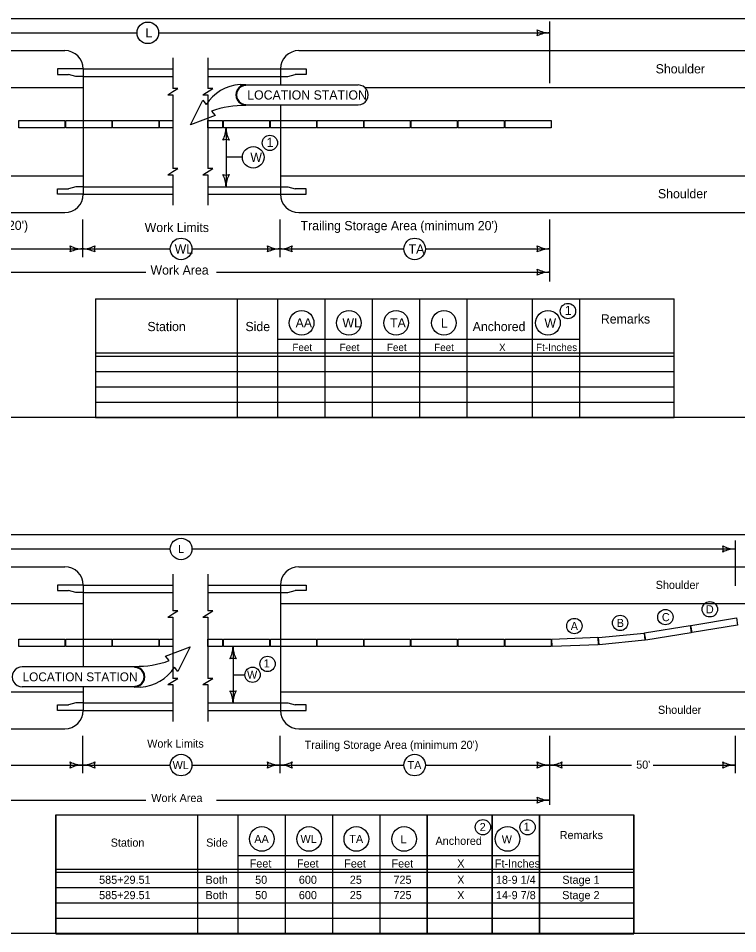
# Model space of a CAD drawing. Extents: x 8045 to 81668, y 6217 to 16762.
# Drawn here: x 14916 to 16087, y 6217 to 7708 of the extents above; entities that cross this region are included whole.
import ezdxf

# ---------------------------------------------------------------- set-up
doc = ezdxf.new("R2010")
doc.units = 0
for name, color, linetype in [('dsnNonPlotable', 7, 'Continuous'), ('dsnStdBlockModified', 7, 'Continuous'), ('dsnStdBlockNotModified', 7, 'Continuous'), ('dsnStdBorder', 7, 'Continuous'), ('dsnStdLineWork', 7, 'Continuous'), ('Level 2', 7, 'Continuous'), ('Level 5', 7, 'Continuous')]:
    doc.layers.add(name, color=color, linetype=linetype)

msp = doc.modelspace()

# ---------------------------------------------------------------- linework, layer by layer
at = {"layer": 'dsnNonPlotable'}
for p, q in [((15781, 7703.1), (15781, 7602.2)), ((14230.5, 7684.4), (15109, 7684.4)), ((15144.3, 7684.4), (15781, 7684.4)), ((13862.8, 7655.5), (14991.3, 7655.5)), ((15372.7, 7655.5), (16721.1, 7655.5)), ((15167.3, 7643.5), (15167.3, 7593.6)), ((15224.4, 7643.5), (15224.4, 7593.6)), ((15021.3, 7625.5), (14979.3, 7625.5)), ((14979.3, 7625.5), (14979.3, 7616.5)), ((15021.3, 7625.5), (15021.3, 7421.5)), ((15021.3, 7625.5), (15167.3, 7625.5)), ((15224.4, 7625.5), (15342.7, 7625.5)), ((15342.7, 7625.5), (15384.7, 7625.5)), ((15342.7, 7625.5), (15342.7, 7599.5)), ((15384.7, 7625.5), (15384.7, 7616.5)), ((14979.3, 7616.5), (14997.3, 7616.5)), ((15009.3, 7613.5), (14997.3, 7616.5)), ((15021.3, 7613.5), (15009.3, 7613.5)), ((15021.3, 7613.5), (15167.3, 7613.5)), ((15224.4, 7613.5), (15342.7, 7613.5)), ((15342.7, 7613.5), (15354.7, 7613.5)), ((15354.7, 7613.5), (15366.7, 7616.5)), ((15384.7, 7616.5), (15366.7, 7616.5)), ((13779.2, 7595.5), (15021.3, 7595.5)), ((15167.3, 7588.6), (15175.3, 7593.6)), ((15175.3, 7593.6), (15167.3, 7593.6)), ((15216.4, 7583.5), (15232.4, 7593.6)), ((15232.4, 7593.6), (15224.4, 7593.6)), ((15276.8, 7600), (15286.3, 7600.4)), ((15286.3, 7600.4), (15286.3, 7598.6)), ((15286.3, 7599.5), (15469.4, 7599.5)), ((15480.2, 7595.5), (16811.5, 7595.5)), ((15159.3, 7583.5), (15167.3, 7588.6)), ((15159.3, 7583.5), (15167.3, 7583.5)), ((15167.3, 7583.5), (15167.3, 7523.5)), ((15195.9, 7534.5), (15216, 7574.5)), ((15216, 7574.5), (15221.6, 7567.5)), ((15216.4, 7583.5), (15224.4, 7583.5)), ((15224.4, 7583.5), (15224.4, 7523.5)), ((15286.3, 7567.9), (15286.3, 7566.1)), ((15286.3, 7567), (15469.4, 7567)), ((15342.7, 7567), (15342.7, 7421.5)), ((15236.1, 7549.5), (15195.9, 7534.5)), ((15230.2, 7556.8), (15236.1, 7549.5)), ((15254, 7529.8), (15254, 7433.5)), ((15167.3, 7523.5), (15167.3, 7463.4)), ((15224.4, 7523.5), (15224.4, 7463.4)), ((15280.6, 7481.6), (15254, 7481.6)), ((15159.3, 7453.3), (15167.3, 7458.4)), ((15167.3, 7458.4), (15175.3, 7463.4)), ((15175.3, 7463.4), (15167.3, 7463.4)), ((15216.4, 7453.3), (15232.4, 7463.4)), ((15232.4, 7463.4), (15224.4, 7463.4)), ((13779.2, 7451.5), (15021.3, 7451.5)), ((15159.3, 7453.3), (15167.3, 7453.3)), ((15167.3, 7453.3), (15167.3, 7403.5)), ((15216.4, 7453.3), (15224.4, 7453.3)), ((15224.4, 7453.3), (15224.4, 7403.5)), ((15342.7, 7451.5), (16811.5, 7451.5)), ((14979.3, 7430.5), (14997.3, 7430.5)), ((14979.3, 7421.5), (14979.3, 7430.5)), ((15009.3, 7433.5), (14997.3, 7430.5)), ((15021.3, 7433.5), (15009.3, 7433.5)), ((15021.3, 7433.5), (15167.3, 7433.5)), ((15224.4, 7433.5), (15342.7, 7433.5)), ((15342.7, 7433.5), (15354.7, 7433.5)), ((15354.7, 7433.5), (15366.7, 7430.5)), ((15384.7, 7430.5), (15366.7, 7430.5)), ((15384.7, 7421.5), (15384.7, 7430.5)), ((15021.3, 7421.5), (14979.3, 7421.5)), ((15021.3, 7421.5), (15167.3, 7421.5)), ((15224.4, 7421.5), (15342.7, 7421.5)), ((15342.7, 7421.5), (15384.7, 7421.5)), ((13862.8, 7391.5), (14991.3, 7391.5)), ((15372.7, 7391.5), (16721.1, 7391.5)), ((15020.1, 7380.2), (15020.1, 7319)), ((15341.5, 7380.2), (15341.5, 7319)), ((15781, 7380.2), (15781, 7279.4)), ((14794, 7332.4), (15020.1, 7332.4)), ((15020.1, 7332.4), (15163.3, 7332.4)), ((15198.3, 7332.4), (15341.5, 7332.4)), ((15211, 7332.4), (15341.5, 7332.4)), ((15341.5, 7332.4), (15543.6, 7332.4)), ((15578.9, 7332.4), (15781, 7332.4)), ((14532.6, 7294.5), (15123.4, 7294.5)), ((15238.7, 7294.5), (15781, 7294.5)), ((15240.1, 7294.5), (15341.5, 7294.5)), ((15272.6, 7058), (15272.6, 7251)), ((15338.6, 7058), (15338.6, 7251)), ((15415.6, 7058), (15415.6, 7251)), ((15492.6, 7058), (15492.6, 7251)), ((15569.6, 7058), (15569.6, 7251)), ((15338.6, 7185.2), (15830.1, 7185.2)), ((15041.6, 7163), (15984.1, 7163)), ((15041.6, 7158), (15984.1, 7158))]:
    msp.add_line(p, q, dxfattribs=at)
for points in [[(14916.3, 7541.8), (14991.3, 7541.8), (14991.3, 7529.8), (14916.3, 7529.8)], [(14992.8, 7541.8), (15067.8, 7541.8), (15067.8, 7529.8), (14992.8, 7529.8)], [(15069.3, 7541.8), (15144.3, 7541.8), (15144.3, 7529.8), (15069.3, 7529.8)], [(15249.7, 7541.8), (15324.7, 7541.8), (15324.7, 7529.8), (15249.7, 7529.8)], [(15326.2, 7541.8), (15401.2, 7541.8), (15401.2, 7529.8), (15326.2, 7529.8)], [(15402.7, 7541.8), (15477.7, 7541.8), (15477.7, 7529.8), (15402.7, 7529.8)], [(15479.2, 7541.8), (15554.2, 7541.8), (15554.2, 7529.8), (15479.2, 7529.8)], [(15555.7, 7541.8), (15630.7, 7541.8), (15630.7, 7529.8), (15555.7, 7529.8)], [(15632.2, 7541.8), (15707.2, 7541.8), (15707.2, 7529.8), (15632.2, 7529.8)], [(15708.7, 7541.8), (15783.7, 7541.8), (15783.7, 7529.8), (15708.7, 7529.8)]]:
    msp.add_lwpolyline(points, close=True, dxfattribs=at)
for points in [[(15167.3, 7529.8), (15145.8, 7529.8), (15145.8, 7541.8), (15167.3, 7541.8)], [(15167.3, 7541.8), (15167.3, 7529.8)], [(15224.4, 7529.8), (15224.4, 7541.8)], [(15224.4, 7541.8), (15248.2, 7541.8), (15248.2, 7529.8), (15224.4, 7529.8)]]:
    msp.add_lwpolyline(points, dxfattribs=at)
for centre, radius in [((15126.6, 7684.4), 17.6), ((15325.4, 7505.1), 12.5), ((15298.3, 7481.6), 17.6), ((15180.8, 7332.4), 17.6), ((15561.3, 7332.4), 17.6), ((15377.1, 7212), 20.1), ((15454.1, 7212), 20.1), ((15531.1, 7212), 20.1), ((15608.9, 7212), 20.1), ((15778.4, 7212), 20.1), ((15811, 7231.2), 12.5)]:
    msp.add_circle(centre, radius, dxfattribs=at)
for centre, radius, start, end in [((15745.4, 7684.4), 16.4, 342.2666, 17.7333), ((15781, 7726.9), 42.5, 241.9275, 270), ((15781, 7641.9), 42.5, 90, 118.0725), ((14991.3, 7625.5), 30, 0, 90), ((15372.7, 7625.5), 30, 90, 180), ((15211.5, 7529.8), 42.5, 331.9275, 0), ((15296.5, 7529.8), 42.5, 180, 208.0725), ((15254, 7494.1), 16.4, 72.2666, 107.7334), ((15254, 7469.1), 16.4, 252.2666, 287.7334), ((15211.5, 7433.5), 42.5, 0, 28.0725), ((15296.5, 7433.5), 42.5, 151.9275, 180), ((14991.3, 7421.5), 30, 270, 360), ((15372.7, 7421.5), 30, 180, 270), ((14984.5, 7332.4), 16.4, 342.2666, 17.7333), ((15020.1, 7374.9), 42.5, 241.9275, 270), ((15020.1, 7374.9), 42.5, 270, 298.0725), ((15055.8, 7332.4), 16.4, 162.2666, 197.7334), ((15305.9, 7332.4), 16.4, 342.2666, 17.7333), ((15341.5, 7374.9), 42.5, 241.9275, 270), ((15341.5, 7374.9), 42.5, 270, 298.0725), ((15377.1, 7332.4), 16.4, 162.2666, 197.7334), ((15745.4, 7332.4), 16.4, 342.2666, 17.7333), ((15781, 7374.9), 42.5, 241.9275, 270), ((15020.1, 7289.9), 42.5, 90, 118.0725), ((15020.1, 7289.9), 42.5, 61.9275, 90), ((15341.5, 7289.9), 42.5, 90, 118.0725), ((15341.5, 7289.9), 42.5, 61.9275, 90), ((15781, 7289.9), 42.5, 90, 118.0725), ((15745.4, 7294.5), 16.4, 342.2666, 17.7333), ((15781, 7337), 42.5, 241.9275, 270), ((15781, 7252), 42.5, 90, 118.0725)]:
    msp.add_arc(centre, radius, start, end, dxfattribs=at)
for centre, major_axis, start_param, end_param in [((15281.3, 7529.7), (-70.8, 0), 4.776871, 5.71778), ((15286.3, 7583.2), (-16.3, 0), 4.712389, 7.853982), ((15286.3, 7583.2), (15.4, 0), 1.570796, 4.712389), ((15469.4, 7583.2), (16.3, 0), 4.712389, 7.853982), ((15283.5, 7410), (-156.9, 0), 4.694293, 5.059134)]:
    msp.add_ellipse(centre, major_axis=major_axis, ratio=0.995025, start_param=start_param, end_param=end_param, dxfattribs=at)
at = {"layer": 'dsnStdBlockModified'}
msp.add_line((13747.5, 7708), (16852.5, 7708), dxfattribs=at)
at = {"layer": 'dsnStdBlockNotModified'}
for p, q in [((15041.6, 7133), (15984.1, 7133)), ((15041.6, 7108), (15984.1, 7108)), ((15041.6, 7083), (15984.1, 7083)), ((15041.6, 7058), (15984.1, 7058))]:
    msp.add_line(p, q, dxfattribs=at)
at = {"layer": 'dsnStdBorder'}
msp.add_line((16852.5, 7058), (13747.5, 7058), dxfattribs=at)
at = {"layer": 'dsnStdLineWork'}
for p, q in [((13747.5, 6867.4), (16852.5, 6867.4)), ((14230.5, 6843.7), (15163.3, 6843.7)), ((15198.3, 6843.7), (16083.2, 6843.7)), ((15211, 6843.7), (15341.5, 6843.7)), ((16083.2, 6857.6), (16083.2, 6783.9)), ((13862.8, 6814.8), (14991.3, 6814.8)), ((15372.7, 6814.8), (16721.1, 6814.8)), ((15167.3, 6802.8), (15167.3, 6742.8)), ((15224.4, 6802.8), (15224.4, 6742.8)), ((15021.3, 6784.8), (14979.3, 6784.8)), ((14979.3, 6784.8), (14979.3, 6775.8)), ((15021.3, 6784.8), (15167.3, 6784.8)), ((15021.3, 6784.8), (15021.3, 6651.7)), ((15224.4, 6784.8), (15342.7, 6784.8)), ((15342.7, 6784.8), (15384.7, 6784.8)), ((15342.7, 6784.8), (15342.7, 6580.8)), ((15384.7, 6784.8), (15384.7, 6775.8)), ((14979.3, 6775.8), (14997.3, 6775.8)), ((15009.3, 6772.8), (14997.3, 6775.8)), ((15021.3, 6772.8), (15009.3, 6772.8)), ((15021.3, 6772.8), (15167.3, 6772.8)), ((15224.4, 6772.8), (15342.7, 6772.8)), ((15342.7, 6772.8), (15354.7, 6772.8)), ((15354.7, 6772.8), (15366.7, 6775.8)), ((15384.7, 6775.8), (15366.7, 6775.8)), ((13779.2, 6754.8), (15021.3, 6754.8)), ((15342.7, 6754.8), (16811.5, 6754.8)), ((15167.3, 6737.8), (15175.3, 6742.8)), ((15175.3, 6742.8), (15167.3, 6742.8)), ((15216.4, 6732.7), (15232.4, 6742.8)), ((15232.4, 6742.8), (15224.4, 6742.8)), ((15159.3, 6732.7), (15167.3, 6737.8)), ((15159.3, 6732.7), (15167.3, 6732.7)), ((15167.3, 6732.7), (15167.3, 6682.8)), ((15216.4, 6732.7), (15224.4, 6732.7)), ((15224.4, 6732.7), (15224.4, 6682.8)), ((15155.5, 6669.2), (15195.7, 6684.2)), ((15167.3, 6682.8), (15167.3, 6632.8)), ((15195.7, 6684.2), (15175.6, 6644.2)), ((15224.4, 6682.8), (15224.4, 6632.8)), ((15265.4, 6684.8), (15265.4, 6592.8)), ((15161.4, 6661.8), (15155.5, 6669.2)), ((15105.2, 6651.7), (14922.1, 6651.7)), ((15105.2, 6650.8), (15105.2, 6652.6)), ((15175.6, 6644.2), (15169.9, 6651.2)), ((15265.4, 6638.8), (15284.7, 6638.8)), ((15159.3, 6622.7), (15167.3, 6627.8)), ((15159.3, 6622.7), (15167.3, 6622.7)), ((15167.3, 6627.8), (15175.3, 6632.8)), ((15175.3, 6632.8), (15167.3, 6632.8)), ((15167.3, 6622.7), (15167.3, 6562.8)), ((15216.4, 6622.7), (15232.4, 6632.8)), ((15216.4, 6622.7), (15224.4, 6622.7)), ((15232.4, 6632.8), (15224.4, 6632.8)), ((15224.4, 6622.7), (15224.4, 6562.8)), ((13779.2, 6610.8), (15021.3, 6610.8)), ((15105.2, 6619.2), (14922.1, 6619.2)), ((15021.3, 6619.2), (15021.3, 6580.8)), ((15105.2, 6618.3), (15105.2, 6620.1)), ((15114.7, 6618.6), (15105.2, 6618.3)), ((15342.7, 6610.8), (16811.5, 6610.8)), ((15009.3, 6592.8), (14997.3, 6589.8)), ((15021.3, 6592.8), (15009.3, 6592.8)), ((15021.3, 6592.8), (15167.3, 6592.8)), ((15224.4, 6592.8), (15342.7, 6592.8)), ((15342.7, 6592.8), (15354.7, 6592.8)), ((15354.7, 6592.8), (15366.7, 6589.8)), ((14979.3, 6589.8), (14997.3, 6589.8)), ((14979.3, 6580.8), (14979.3, 6589.8)), ((15021.3, 6580.8), (14979.3, 6580.8)), ((15021.3, 6580.8), (15167.3, 6580.8)), ((15224.4, 6580.8), (15342.7, 6580.8)), ((15342.7, 6580.8), (15384.7, 6580.8)), ((15384.7, 6589.8), (15366.7, 6589.8)), ((15384.7, 6580.8), (15384.7, 6589.8)), ((13862.8, 6550.8), (14991.3, 6550.8)), ((15372.7, 6550.8), (16721.1, 6550.8)), ((15020.1, 6539.5), (15020.1, 6478.3)), ((15341.5, 6539.5), (15341.5, 6478.3)), ((15781, 6539.5), (15781, 6427.1)), ((16083.2, 6539.5), (16083.2, 6478.3)), ((14794, 6491.7), (15020.1, 6491.7)), ((15020.1, 6491.7), (15163.3, 6491.7)), ((15198.3, 6491.7), (15341.5, 6491.7)), ((15211, 6491.7), (15341.5, 6491.7)), ((15341.5, 6491.7), (15543.6, 6491.7)), ((15578.9, 6491.7), (15781, 6491.7)), ((15781, 6491.7), (15914.4, 6491.7)), ((15949.7, 6491.7), (16083.2, 6491.7)), ((14532.6, 6434.6), (15123.4, 6434.6)), ((15238.7, 6434.6), (15781, 6434.6)), ((15240.1, 6434.6), (15341.5, 6434.6)), ((14976.8, 6410.4), (14976.8, 6217.4)), ((14976.8, 6410.4), (15918.4, 6410.4)), ((14976.8, 6217.4), (14976.8, 6410.4)), ((14976.8, 6410.4), (15918.4, 6410.4)), ((15207.8, 6217.4), (15207.8, 6410.4)), ((15273.8, 6217.4), (15273.8, 6410.4)), ((15350.8, 6217.4), (15350.8, 6410.4)), ((15427.8, 6217.4), (15427.8, 6410.4)), ((15504.8, 6217.4), (15504.8, 6410.4)), ((15581.8, 6217.4), (15581.8, 6410.4)), ((15581.8, 6410.4), (15581.8, 6217.4)), ((15687.4, 6217.4), (15687.4, 6410.4)), ((15687.4, 6410.4), (15687.4, 6217.4)), ((15764.4, 6217.4), (15764.4, 6410.4)), ((15764.4, 6410.4), (15764.4, 6217.4)), ((15918.4, 6217.4), (15918.4, 6410.4)), ((15918.4, 6410.4), (15918.4, 6217.4)), ((15273.8, 6344.6), (15764.4, 6344.6)), ((14976.8, 6322.4), (15918.4, 6322.4)), ((14976.8, 6317.4), (15918.4, 6317.4)), ((14976.8, 6292.4), (15918.4, 6292.4)), ((14976.8, 6267.4), (15918.4, 6267.4)), ((14976.8, 6242.4), (15918.4, 6242.4)), ((16852.5, 6217.4), (13747.5, 6217.4)), ((14976.8, 6217), (15918.4, 6217))]:
    msp.add_line(p, q, dxfattribs=at)
for points in [[(16011.4, 6719.3), (16085.4, 6731.4), (16087.4, 6719.6), (16013.4, 6707.5)], [(15935.9, 6706.9), (16009.9, 6719.1), (16011.9, 6707.2), (15937.9, 6695.1)], [(14916.3, 6696.8), (14991.3, 6696.8), (14991.3, 6684.8), (14916.3, 6684.8)], [(14992.8, 6696.8), (15067.8, 6696.8), (15067.8, 6684.8), (14992.8, 6684.8)], [(15069.3, 6696.8), (15144.3, 6696.8), (15144.3, 6684.8), (15069.3, 6684.8)], [(15249.7, 6696.8), (15324.7, 6696.8), (15324.7, 6684.8), (15249.7, 6684.8)], [(15326.2, 6696.8), (15401.2, 6696.8), (15401.2, 6684.8), (15326.2, 6684.8)], [(15402.7, 6696.8), (15477.7, 6696.8), (15477.7, 6684.8), (15402.7, 6684.8)], [(15479.2, 6696.8), (15554.2, 6696.8), (15554.2, 6684.8), (15479.2, 6684.8)], [(15555.7, 6696.8), (15630.7, 6696.8), (15630.7, 6684.8), (15555.7, 6684.8)], [(15632.2, 6696.8), (15707.2, 6696.8), (15707.2, 6684.8), (15632.2, 6684.8)], [(15708.7, 6696.8), (15783.7, 6696.8), (15783.7, 6684.8), (15708.7, 6684.8)], [(15784.7, 6696.8), (15859.7, 6699.8), (15860.2, 6687.8), (15785.2, 6684.8)], [(15860.5, 6699.7), (15935.2, 6706.8), (15936.3, 6694.9), (15861.7, 6687.8)]]:
    msp.add_lwpolyline(points, close=True, dxfattribs=at)
for points in [[(15167.3, 6684.8), (15145.8, 6684.8), (15145.8, 6696.8), (15167.3, 6696.8)], [(15167.3, 6696.8), (15167.3, 6684.8)], [(15224.4, 6684.8), (15224.4, 6696.8)], [(15224.4, 6696.8), (15248.2, 6696.8), (15248.2, 6684.8), (15224.4, 6684.8)]]:
    msp.add_lwpolyline(points, dxfattribs=at)
for centre, radius in [((15180.8, 6843.7), 17.6), ((16042.1, 6745.4), 12.5), ((15969.7, 6732.7), 12.5), ((15821.4, 6718.2), 12.5), ((15896, 6723.2), 12.5), ((15321.6, 6656.4), 12.5), ((15297.2, 6638.8), 12.5), ((15180.8, 6491.7), 17.6), ((15561.3, 6491.7), 17.6), ((15672.4, 6390.5), 12.5), ((15745.2, 6390.5), 12.5), ((15312.3, 6371.4), 20.1), ((15389.3, 6371.4), 20.1), ((15466.3, 6371.4), 20.1), ((15544.1, 6371.4), 20.1), ((15712.6, 6371.4), 20.1)]:
    msp.add_circle(centre, radius, dxfattribs=at)
for centre, radius, start, end in [((16047.5, 6843.7), 16.4, 342.2666, 17.7333), ((16083.2, 6886.2), 42.5, 241.9275, 270), ((16083.2, 6801.2), 42.5, 90, 118.0725), ((14991.3, 6784.8), 30, 0, 90), ((15372.7, 6784.8), 30, 90, 180), ((15222.9, 6684.8), 42.5, 331.9275, 360), ((15307.9, 6684.8), 42.5, 180, 208.0725), ((15265.4, 6649.1), 16.4, 72.2666, 107.7334), ((15265.4, 6628.4), 16.4, 252.2666, 287.7333), ((15222.9, 6592.8), 42.5, 360, 28.0725), ((15307.9, 6592.8), 42.5, 151.9275, 180), ((14991.3, 6580.8), 30, 270, 360), ((15372.7, 6580.8), 30, 180, 270), ((14984.5, 6491.7), 16.4, 342.2666, 17.7333), ((15020.1, 6534.2), 42.5, 241.9275, 270), ((15020.1, 6449.2), 42.5, 90, 118.0725), ((15020.1, 6534.2), 42.5, 270, 298.0725), ((15020.1, 6449.2), 42.5, 61.9275, 90), ((15055.8, 6491.7), 16.4, 162.2666, 197.7334), ((15305.9, 6491.7), 16.4, 342.2666, 17.7333), ((15341.5, 6534.2), 42.5, 241.9275, 270), ((15341.5, 6449.2), 42.5, 90, 118.0725), ((15341.5, 6534.2), 42.5, 270, 298.0725), ((15341.5, 6449.2), 42.5, 61.9275, 90), ((15377.1, 6491.7), 16.4, 162.2666, 197.7334), ((15745.4, 6491.7), 16.4, 342.2666, 17.7333), ((15781, 6534.2), 42.5, 241.9275, 270), ((15781, 6449.2), 42.5, 90, 118.0725), ((15781, 6534.2), 42.5, 270, 298.0725), ((15781, 6449.2), 42.5, 61.9275, 90), ((15816.6, 6491.7), 16.4, 162.2666, 197.7334), ((16047.5, 6491.7), 16.4, 342.2666, 17.7333), ((16083.2, 6534.2), 42.5, 241.9275, 270), ((16083.2, 6449.2), 42.5, 90, 118.0725), ((15745.4, 6434.6), 16.4, 342.2666, 17.7333), ((15781, 6477.1), 42.5, 241.9275, 270), ((15781, 6392.1), 42.5, 90, 118.0725)]:
    msp.add_arc(centre, radius, start, end, dxfattribs=at)
for centre, major_axis, start_param, end_param in [((14922.1, 6635.4), (-16.3, 0), 4.712389, 7.853982), ((15108.1, 6808.6), (156.9, 0), 4.694293, 5.059134), ((15105.2, 6635.4), (16.3, 0), 4.712389, 7.853982), ((15105.2, 6635.4), (-15.4, 0), 1.570796, 4.712389), ((15110.2, 6688.9), (70.8, 0), 4.776871, 5.71778)]:
    msp.add_ellipse(centre, major_axis=major_axis, ratio=0.995025, start_param=start_param, end_param=end_param, dxfattribs=at)
at = {"layer": 'Level 2'}
for p, q in [((15041.6, 7251), (15041.6, 7058)), ((15041.6, 7251), (15984.1, 7251)), ((15646.6, 7058), (15646.6, 7251)), ((15753.1, 7058), (15753.1, 7251)), ((15830.1, 7058), (15830.1, 7251)), ((15984.1, 7058), (15984.1, 7251))]:
    msp.add_line(p, q, dxfattribs=at)

# ---------------------------------------------------------------- texts
at = {"layer": 'dsnStdLineWork'}
for s, height, p in [('L', 13.2, (15176, 6837.1)), ('Shoulder', 13.2, (15953.9, 6778.6)), ('C', 13.2, (15964, 6726.1)), ('D', 13.2, (16035.7, 6738.8)), ('A', 13.2, (15815.5, 6711.6)), ('B', 13.2, (15890.5, 6716.6)), ('1', 13.2, (15315.3, 6650.7)), ('LOCATION STATION', 14.4, (14922.5, 6628.2)), ('W', 13.2, (15288.2, 6632.2)), ('Shoulder', 13.2, (15957.6, 6575.1)), ('Work Limits', 13.2, (15125.5, 6520.1)), ("Trailing Storage Area (minimum 20')", 13.2, (15382, 6518.1)), ('WL', 13.2, (15166.9, 6485.1)), ('TA', 13.2, (15549.7, 6485.1)), ("50'", 13.2, (15922.1, 6485.8)), ('Work Area', 13.2, (15132.2, 6431.6)), ('2', 13.2, (15667.2, 6384.2)), ('1', 13.2, (15738.9, 6384.8)), ('Remarks', 13.2, (15797.5, 6371.1)), ('Station', 13.2, (15066.1, 6358.8)), ('Side', 13.2, (15221.6, 6358.8)), ('AA', 13.2, (15300.1, 6364.8)), ('WL', 13.2, (15375.3, 6364.8)), ('TA', 13.2, (15454.8, 6364.8)), ('L', 13.2, (15538.2, 6364.3)), ('Anchored', 13.2, (15595.2, 6361.7)), ('W', 13.2, (15703.1, 6364.3)), ('Feet', 13.2, (15292.5, 6324.8)), ('Feet', 13.2, (15369.5, 6324.8)), ('Feet', 13.2, (15446.5, 6324.8)), ('Feet', 13.2, (15523.5, 6324.8)), ('X', 13.2, (15630.6, 6324.8)), ('Ft-Inches', 13.2, (15691.9, 6324.8)), ('585+29.51', 13.2, (15047.2, 6298.3)), ('Both', 13.2, (15220.6, 6298.3)), ('50', 13.2, (15301.4, 6298.3)), ('600', 13.2, (15372.6, 6298.3)), ('25', 13.2, (15455.6, 6298.3)), ('725', 13.2, (15526.7, 6298.3)), ('X', 13.2, (15630.6, 6298.3)), ('18-9 1/4', 13.2, (15693.6, 6298.3)), ('Stage 1', 13.2, (15801.8, 6298.3)), ('585+29.51', 13.2, (15047.2, 6273.3)), ('Both', 13.2, (15220.6, 6273.3)), ('50', 13.2, (15301.4, 6273.3)), ('600', 13.2, (15372.6, 6273.3)), ('25', 13.2, (15455.6, 6273.3)), ('725', 13.2, (15526.7, 6273.3)), ('X', 13.2, (15630.6, 6273.3)), ('14-9 7/8', 13.2, (15693.7, 6273.3)), ('Stage 2', 13.2, (15801.6, 6273.3))]:
    msp.add_text(s, height=height, dxfattribs=at).set_placement(p)
at = {"layer": 'Level 5'}
for s, height, p in [('L', 15, (15122.7, 7676.9)), ('Shoulder', 15, (15953.9, 7618.3)), ('LOCATION STATION', 15, (15288.5, 7575.7)), ('1', 15, (15320.1, 7498.5)), ('W', 15, (15293.6, 7474.1)), ('Shoulder', 15, (15957.6, 7414.9)), ("Approach Storage Area (minimum 20')", 15, (14589.9, 7363.3)), ('Work Limits', 15, (15121.4, 7359.9)), ("Trailing Storage Area (minimum 20')", 15, (15375.4, 7362.9)), ('WL', 15, (15170.3, 7324.9)), ('TA', 15, (15551.4, 7324.9)), ('Work Area', 15, (15130.9, 7290.6)), ('1', 15, (15805.8, 7224.6)), ('AA', 15, (15367.3, 7204.5)), ('WL', 15, (15443.6, 7204.5)), ('TA', 15, (15521.2, 7204.5)), ('L', 15, (15604, 7204.1)), ('W', 15, (15772.7, 7204.1)), ('Remarks', 15, (15864.6, 7210.9)), ('Station', 15, (15125.9, 7198.5)), ('Side', 15, (15285.6, 7198.5)), ('Anchored', 15, (15655.8, 7198.5)), ('Feet', 12, (15362.1, 7166)), ('Feet', 12, (15439.1, 7166)), ('Feet', 12, (15516.1, 7166)), ('Feet', 12, (15593.1, 7166)), ('X', 12, (15698.7, 7166)), ('Ft-Inches', 12, (15759.1, 7166))]:
    msp.add_text(s, height=height, dxfattribs=at).set_placement(p)

doc.saveas('drawing.dxf')
